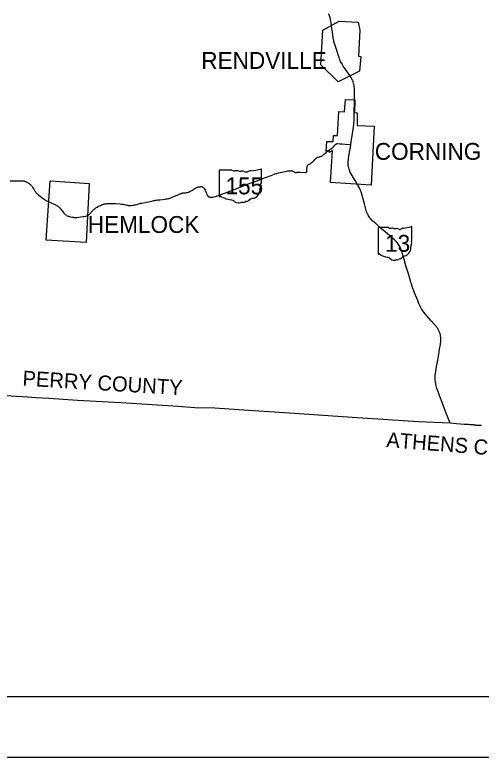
# Model space of a CAD drawing. Extents: x 1912787 to 2184787, y 543251 to 719251.
# Drawn here: x 2062306 to 2093246, y 543251 to 592546 of the extents above; entities that cross this region are included whole.
import ezdxf

# ---------------------------------------------------------------- set-up
doc = ezdxf.new("R2010")
doc.units = 0
for name, color, linetype in [('GM_X_Corporation', 7, 'Continuous'), ('GM_X_Corporation_Text', 7, 'Continuous'), ('GM_X_County', 7, 'Continuous'), ('GM_X_County_Text', 7, 'Continuous'), ('GM_X_State_Location', 7, 'Continuous'), ('GM_X_State_Route', 7, 'Continuous'), ('GM_X_State_Shield', 7, 'Continuous'), ('SH_Border', 7, 'Continuous'), ('SH_Cut_Line', 7, 'Continuous')]:
    doc.layers.add(name, color=color, linetype=linetype)

msp = doc.modelspace()

# ---------------------------------------------------------------- linework, layer by layer
at = {"layer": 'GM_X_Corporation'}
for points in [[(2085094, 592066), (2085207, 591526), (2085112, 589795), (2085262, 589789), (2085180, 588802), (2083763, 588102), (2082607, 589216), (2082738, 591533), (2083820, 592122)], [(2084871, 586911), (2084833, 586071), (2085029, 586048), (2085021, 585202), (2086138, 585145), (2085942, 581237), (2083259, 581417), (2083381, 583529), (2083192, 583401), (2083158, 583561), (2082965, 583472), (2083004, 584136), (2083419, 584138), (2083442, 584534), (2083720, 584528), (2083814, 586125), (2084179, 586110), (2084247, 586917)], [(2067028, 577432), (2064389, 577580), (2064656, 581515), (2067233, 581351)]]:
    msp.add_lwpolyline(points, close=True, dxfattribs=at)
at = {"layer": 'GM_X_County'}
msp.add_lwpolyline([(2093279, 565284), (2093242, 565282), (2093202, 565278), (2093174, 565277), (2093157, 565276), (2093138, 565274), (2093117, 565273), (2093087, 565272), (2093062, 565271), (2093044, 565270), (2093029, 565271), (2093011, 565272), (2092991, 565273), (2092975, 565275), (2092959, 565277), (2092942, 565279), (2092915, 565283), (2092886, 565288), (2092851, 565294), (2092806, 565302), (2092773, 565307), (2092745, 565311), (2092717, 565314), (2092689, 565317), (2092668, 565319), (2092646, 565321), (2092612, 565323), (2092582, 565324), (2092547, 565326), (2092501, 565329), (2092398, 565335), (2092306, 565340), (2092184, 565344), (2092117, 565345), (2091608, 565393), (2091183, 565423), (2089083, 565522), (2084678, 565800), (2080230, 566127), (2077809, 566264), (2075585, 566435), (2074254, 566448), (2073129, 566535), (2071764, 566629), (2069342, 566782), (2066457, 566938), (2064570, 567061), (2063710, 567111), (2063147, 567149), (2059524, 567388)], dxfattribs=at)
at = {"layer": 'GM_X_State_Route'}
msp.add_line((2083189, 592470), (2083138, 592619), dxfattribs=at)
for points in [[(2083257, 592245), (2083231, 592345), (2083211, 592409), (2083189, 592470)], [(2083316, 591845), (2083302, 591947), (2083299, 591972), (2083275, 592139), (2083257, 592245)], [(2084612, 588386), (2084551, 588480), (2084479, 588585), (2084317, 588821), (2084218, 588968), (2084094, 589144), (2084038, 589231), (2083993, 589308), (2083950, 589390), (2083924, 589447), (2083898, 589506), (2083858, 589612), (2083815, 589733), (2083785, 589825), (2083670, 590180), (2083539, 590581), (2083518, 590649), (2083482, 590777), (2083463, 590858), (2083457, 590893), (2083433, 591023), (2083377, 591410), (2083348, 591616), (2083316, 591845)], [(2084836, 586931), (2084837, 587191), (2084841, 587479), (2084841, 587586), (2084837, 587678), (2084829, 587773), (2084818, 587851), (2084818, 587856), (2084801, 587932), (2084780, 588014), (2084753, 588098), (2084728, 588159), (2084714, 588192), (2084663, 588297), (2084615, 588381), (2084612, 588386)], [(2085003, 581348), (2084970, 581400), (2084887, 581537), (2084726, 581799), (2084680, 581871), (2084619, 581982), (2084566, 582083), (2084539, 582139), (2084527, 582173), (2084505, 582229), (2084481, 582304), (2084457, 582396), (2084441, 582483), (2084433, 582543), (2084428, 582589), (2084423, 582662), (2084423, 582765), (2084428, 582836), (2084436, 582904), (2084447, 582996), (2084497, 583300), (2084591, 583900), (2084598, 583939), (2084650, 584242), (2084738, 584806), (2084785, 585096), (2084809, 585286), (2084821, 585531), (2084826, 585916), (2084830, 586339), (2084834, 586509), (2084836, 586915), (2084836, 586931)], [(2083259, 583641), (2083279, 583656), (2083328, 583689), (2083371, 583717), (2083402, 583740), (2083418, 583754), (2083434, 583771), (2083449, 583788), (2083462, 583803), (2083534, 583889), (2083563, 583917), (2083585, 583935), (2083609, 583955), (2083629, 583969), (2083641, 583978), (2083656, 583985), (2083671, 583989), (2083695, 583993), (2083720, 583994), (2083864, 583988), (2084009, 583977)], [(2084009, 583977), (2084215, 583962), (2084598, 583939)], [(2075329, 580427), (2075359, 580429), (2075391, 580434), (2075435, 580442), (2075508, 580457), (2075625, 580489), (2075677, 580504), (2075735, 580523), (2075871, 580575), (2076465, 580799), (2076914, 580972), (2077525, 581205), (2077923, 581361), (2078266, 581489), (2078759, 581674), (2078945, 581745), (2079307, 581884), (2079427, 581931), (2079506, 581960), (2079557, 581979), (2079618, 581999), (2079687, 582019), (2079799, 582050), (2080012, 582102), (2080140, 582131), (2080241, 582151), (2080348, 582169), (2080413, 582178), (2080501, 582189), (2080582, 582197), (2080632, 582199), (2080663, 582198), (2080683, 582196), (2080705, 582191), (2080729, 582182), (2080750, 582172), (2080788, 582149), (2080841, 582110), (2080862, 582097), (2080879, 582089), (2080895, 582083), (2080915, 582077), (2080932, 582075), (2080946, 582075), (2080960, 582075), (2080977, 582078), (2080997, 582082), (2081029, 582088), (2081053, 582091), (2081080, 582093), (2081114, 582095), (2081149, 582095), (2081211, 582093), (2081569, 582074), (2081609, 582076), (2081622, 582079), (2081635, 582083), (2081645, 582090), (2081657, 582102), (2081666, 582113), (2081673, 582132), (2081678, 582165), (2081682, 582223), (2081689, 582340), (2081692, 582380), (2081694, 582420), (2081697, 582453), (2081701, 582476), (2081707, 582497), (2081712, 582512), (2081722, 582534), (2081732, 582548), (2081744, 582561), (2081759, 582576), (2081776, 582589), (2081796, 582601), (2081829, 582619), (2081861, 582636), (2081900, 582657), (2081937, 582685), (2081967, 582708), (2082009, 582745), (2082062, 582792), (2082114, 582840), (2082136, 582861), (2082216, 582944), (2082258, 582989), (2082270, 583001), (2082289, 583019), (2082305, 583030), (2082325, 583045), (2082344, 583056), (2082365, 583067), (2082382, 583075), (2082415, 583086), (2082454, 583099), (2082532, 583120), (2082556, 583128), (2082592, 583140), (2082625, 583152), (2082659, 583169), (2082695, 583192), (2082751, 583236), (2082818, 583290), (2082868, 583330), (2082959, 583403), (2082972, 583412)], [(2082972, 583412), (2083037, 583461), (2083092, 583503), (2083137, 583539), (2083186, 583583), (2083214, 583606), (2083243, 583629), (2083259, 583641)], [(2062005, 581516), (2062307, 581520), (2062621, 581523), (2062711, 581523), (2062791, 581523), (2062857, 581520), (2062885, 581519), (2062914, 581515), (2062937, 581510), (2062955, 581505), (2062977, 581498), (2063005, 581488), (2063040, 581472), (2063061, 581463), (2063104, 581442), (2063148, 581417), (2063180, 581397), (2063222, 581369), (2063265, 581339), (2063300, 581312), (2063345, 581270), (2063375, 581242), (2063403, 581212), (2063434, 581173), (2063462, 581137), (2063509, 581066), (2063567, 580971), (2063613, 580886), (2063636, 580849), (2063656, 580816), (2063672, 580790), (2063690, 580765), (2063712, 580737), (2063746, 580700), (2063768, 580677), (2063791, 580656), (2063815, 580634), (2063867, 580590), (2063997, 580486), (2064123, 580388), (2064189, 580340), (2064242, 580303)], [(2091184, 565420), (2091058, 565754), (2090910, 566146), (2090799, 566441), (2090624, 566911), (2090489, 567261), (2090372, 567575), (2090317, 567732), (2090286, 567828), (2090266, 567907), (2090248, 567988), (2090233, 568067), (2090220, 568141), (2090212, 568208), (2090204, 568290), (2090199, 568373), (2090196, 568434), (2090199, 568533), (2090201, 568595), (2090206, 568661), (2090212, 568732), (2090230, 568852), (2090287, 569192), (2090364, 569620), (2090432, 570011), (2090490, 570345), (2090543, 570656), (2090555, 570736), (2090565, 570826), (2090572, 570917), (2090572, 571019), (2090564, 571127), (2090555, 571199), (2090539, 571276), (2090519, 571355), (2090486, 571464), (2090465, 571515), (2090439, 571572), (2090405, 571641), (2090365, 571709), (2090337, 571753), (2090296, 571815), (2090268, 571853), (2090235, 571896), (2090157, 571987), (2089939, 572234), (2089647, 572560), (2089532, 572690), (2089447, 572796), (2089376, 572890), (2089334, 572951), (2089284, 573033), (2089241, 573108), (2089194, 573200), (2089150, 573294), (2089092, 573432), (2089039, 573567), (2088834, 574076), (2088733, 574344), (2088701, 574424), (2088663, 574528), (2088616, 574676), (2088583, 574782), (2088555, 574877), (2088461, 575201), (2088399, 575409), (2088259, 575889), (2088140, 576296), (2088006, 576748), (2087983, 576824), (2087950, 576922), (2087919, 577003), (2087891, 577066), (2087847, 577153), (2087809, 577219), (2087762, 577291), (2087713, 577363), (2087666, 577421), (2087625, 577471), (2087580, 577519), (2087494, 577602), (2087370, 577714), (2087006, 578028), (2086644, 578340), (2086346, 578599), (2086249, 578684), (2086162, 578758), (2086065, 578845), (2085987, 578921), (2085924, 578992), (2085896, 579024), (2085862, 579068), (2085818, 579130), (2085774, 579201), (2085740, 579261), (2085706, 579329), (2085671, 579411), (2085650, 579467), (2085625, 579547), (2085599, 579633), (2085500, 580005), (2085395, 580400), (2085358, 580546), (2085286, 580783), (2085251, 580875), (2085216, 580956), (2085184, 581026), (2085157, 581080), (2085116, 581156), (2085032, 581299), (2085003, 581348)], [(2068610, 580025), (2068665, 580027), (2068778, 580024), (2068982, 580010), (2069296, 579988), (2069382, 579980), (2069427, 579976), (2069469, 579971), (2069498, 579967), (2069534, 579960), (2069587, 579950), (2069661, 579932), (2069732, 579912), (2069768, 579903), (2069793, 579897), (2069831, 579889), (2069882, 579884), (2069923, 579883), (2069971, 579885), (2070018, 579889), (2070102, 579901), (2070202, 579917), (2070261, 579926), (2070320, 579938), (2070396, 579958), (2070463, 579978), (2070635, 580030), (2070683, 580042), (2070722, 580051), (2071158, 580134), (2071394, 580181), (2071513, 580206), (2071592, 580221), (2071644, 580231), (2071705, 580241), (2071790, 580253), (2071918, 580271), (2072271, 580315), (2072340, 580323), (2072406, 580332), (2072470, 580342), (2072535, 580356), (2072590, 580371), (2072647, 580391), (2072794, 580462), (2073077, 580577), (2073158, 580609), (2073222, 580635), (2073311, 580672), (2073358, 580690), (2073393, 580704), (2073422, 580712), (2073449, 580718), (2073486, 580723), (2073623, 580734), (2073692, 580740), (2073721, 580744), (2073754, 580750), (2073789, 580757), (2073828, 580770), (2073865, 580786), (2073942, 580828), (2074041, 580886), (2074173, 580971), (2074267, 581023), (2074304, 581043), (2074361, 581071), (2074390, 581083), (2074421, 581096), (2074449, 581107), (2074474, 581113), (2074498, 581119), (2074541, 581128), (2074595, 581133), (2074640, 581137)], [(2074640, 581137), (2074680, 581137), (2074704, 581135), (2074727, 581132), (2074748, 581127), (2074768, 581119), (2074790, 581107), (2074812, 581092), (2074835, 581068), (2074849, 581048), (2074873, 581008), (2074926, 580893), (2075005, 580716), (2075046, 580631), (2075065, 580593), (2075076, 580570), (2075089, 580549), (2075102, 580531), (2075121, 580510), (2075139, 580493), (2075166, 580473), (2075187, 580461), (2075211, 580450), (2075235, 580441), (2075279, 580431), (2075305, 580427), (2075329, 580427)], [(2064242, 580303), (2064251, 580297), (2064305, 580262), (2064337, 580243), (2064368, 580225), (2064409, 580202), (2064469, 580172), (2064511, 580153), (2064561, 580130), (2064631, 580098), (2064755, 580046)], [(2064755, 580046), (2064810, 580023), (2064975, 579950), (2065002, 579938), (2065044, 579916), (2065080, 579895), (2065118, 579871), (2065155, 579844), (2065179, 579825), (2065212, 579797), (2065245, 579763), (2065280, 579727), (2065313, 579689), (2065349, 579646), (2065408, 579570), (2065479, 579479), (2065529, 579415), (2065561, 579375), (2065594, 579339), (2065626, 579308), (2065657, 579280), (2065681, 579260), (2065704, 579241), (2065723, 579228), (2065741, 579218), (2065768, 579205), (2065829, 579185), (2065869, 579173), (2066005, 579140), (2066138, 579112), (2066187, 579101), (2066215, 579097), (2066248, 579092), (2066281, 579090), (2066326, 579089), (2066377, 579091), (2066435, 579095), (2066549, 579108), (2066694, 579128), (2066847, 579152), (2066862, 579155)], [(2066862, 579155), (2066877, 579158), (2066991, 579181), (2067075, 579201), (2067124, 579215), (2067150, 579227), (2067174, 579239), (2067204, 579257), (2067233, 579280), (2067281, 579325), (2067486, 579546), (2067550, 579618), (2067577, 579646), (2067603, 579671), (2067633, 579701), (2067652, 579718), (2067680, 579740), (2067717, 579762), (2067763, 579785), (2067861, 579832), (2067982, 579893), (2068045, 579922), (2068090, 579943), (2068137, 579962), (2068187, 579976), (2068231, 579987), (2068278, 579996), (2068358, 580006), (2068433, 580014), (2068515, 580020), (2068569, 580024), (2068610, 580025)]]:
    msp.add_lwpolyline(points, dxfattribs=at)
at = {"layer": 'GM_X_State_Shield'}
for p, q in [((2075865, 582209), (2075865, 580507)), ((2076713, 582238), (2075893, 582238)), ((2078667, 581390), (2078667, 582280)), ((2078667, 581390), (2078667, 581390)), ((2086416, 578394), (2086416, 576693)), ((2087095, 578423), (2086438, 578423)), ((2088657, 577575), (2088657, 578465)), ((2088657, 577576), (2088657, 577575))]:
    msp.add_line(p, q, dxfattribs=at)
for centre, radius, start, end in [((2086442, 578397), 26, 98.1301, 188.1301), ((2087251, 578621), 252, 231.6195, 271.1119), ((2087334, 577468), 904, 80.4867, 94.9883), ((2087540, 578406), 72.7, 219.7921, 297.1024), ((2087646, 578210), 151, 54.4667, 119.1411), ((2087841, 578479), 182, 233.8562, 294.8282), ((2088162, 577904), 478, 97.3462, 120.7689), ((2087859, 580742), 2377, 275.8445, 288.9065), ((2088633, 578469), 25, 351.8621, 97.738), ((2088747, 577203), 169, 136.8065, 186.9296), ((2088652, 577510), 38.6, 107.944, 210.337), ((2088406, 577398), 232, 340.033, 23.6496), ((2088631, 577572), 26.7, 289.6038, 7.7341), ((2087992, 577090), 595, 292.3089, 8.9858), ((2086442, 576689), 26.2, 171.9584, 258.3066), ((2086446, 576863), 200, 267.339, 280.6039), ((2086487, 576595), 72.1, 29.7484, 93.2717), ((2087397, 578123), 1716, 240.4129, 257.1985), ((2086885, 575928), 537, 47.1842, 75.836), ((2087466, 576586), 341, 230.7004, 286.2918), ((2087663, 575998), 280, 85.6951, 111.2099), ((2087688, 576459), 182, 268.777, 315.5493), ((2087852, 576294), 51.1, 65.7517, 132.6484), ((2087830, 576528), 192, 282.8732, 323.2771), ((2088243, 576215), 326, 94.4031, 142.5768)]:
    msp.add_arc(centre, radius, start, end, dxfattribs=at)
for centre, major_axis, start_param, end_param in [((2075898, 582212), (32.5, 0), 1.712693, 3.28349), ((2076909, 582435), (315, 0), 4.042523, 4.731795), ((2077013, 581283), (1130, 0), 1.404758, 1.657858), ((2077403, 582024), (189, 0), 0.950623, 2.079405), ((2078048, 581718), (598, 0), 1.699011, 2.107814), ((2077669, 584557), (2971, 0), 4.814394, 5.042369), ((2078636, 582284), (31.2, 0), 6.141152, 7.989035), ((2077270, 582221), (90.8, 0), 3.836095, 5.185415), ((2077647, 582294), (227, 0), 4.081561, 5.145723), ((2078660, 581325), (48.3, 0), 1.883978, 3.671073), ((2078353, 581212), (290, 0), 5.934695, 6.695948), ((2078634, 581387), (33.4, 0), 5.05454, 6.418171), ((2077836, 580905), (743, 0), 5.101752, 6.440018), ((2078779, 581018), (211, 0), 2.387724, 3.262537), ((2075898, 580504), (32.7, 0), 3.00124, 4.508301), ((2075903, 580678), (250, 0), 4.665946, 4.897461), ((2075954, 580409), (90.1, 0), 0.519207, 1.627899), ((2077092, 581938), (2146, 0), 4.195997, 4.488961), ((2076452, 579743), (671, 0), 0.823519, 1.323587), ((2077633, 580343), (240, 0), 4.937069, 5.64225), ((2078149, 580030), (407, 0), 1.647645, 2.488434), ((2077178, 580401), (426, 0), 4.026481, 4.996735), ((2077424, 579813), (350, 0), 1.495662, 1.94098), ((2077455, 580273), (227, 0), 4.691044, 5.507374), ((2077660, 580109), (63.9, 0), 1.147584, 2.315152)]:
    msp.add_ellipse(centre, major_axis=major_axis, ratio=0.8, start_param=start_param, end_param=end_param, dxfattribs=at)
at = {"layer": 'SH_Border'}
msp.add_lwpolyline([(1924787, 715251), (2180787, 715251), (2180787, 547251), (1924787, 547251)], close=True, dxfattribs=at)
at = {"layer": 'SH_Cut_Line'}
msp.add_lwpolyline([(1912787, 543251), (2184787, 543251), (2184787, 719251), (1912787, 719251)], close=True, dxfattribs=at)

# ---------------------------------------------------------------- texts
at = {"layer": 'GM_X_Corporation_Text'}
for s, p in [('RENDVILLE', (2074676, 588956)), ('CORNING', (2086188, 582917)), ('HEMLOCK', (2067145, 578063))]:
    msp.add_text(s, height=1120, rotation=0, dxfattribs=at).set_placement(p)
at = {"layer": 'GM_X_County_Text'}
for s, rotation, p in [('PERRY COUNTY', 356.5487, (2062791, 567925)), ('ATHENS COUNTY', 355.5123, (2086932, 563846))]:
    msp.add_text(s, height=1000, rotation=rotation, dxfattribs=at).set_placement(p)
at = {"layer": 'GM_X_State_Location'}
for s, p in [('155', (2076895, 580938)), ('13', (2087270, 577123))]:
    msp.add_text(s, height=1, rotation=0, dxfattribs=at).set_placement(p)
for s, p in [('s', (2077248, 581011)), ('r', (2077248, 581011)), ('s', (2087522, 577196)), ('r', (2087522, 577196))]:
    msp.add_text(s, height=1, dxfattribs=at).set_placement(p)
at = {"layer": 'GM_X_State_Shield'}
for s, p in [('155', (2076283, 580627)), ('13', (2086872, 576813))]:
    msp.add_text(s, height=1120.7, dxfattribs=at).set_placement(p)

doc.saveas('drawing.dxf')
